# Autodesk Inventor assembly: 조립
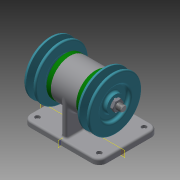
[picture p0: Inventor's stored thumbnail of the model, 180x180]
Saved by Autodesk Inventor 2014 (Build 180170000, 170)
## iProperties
Created: 2019-09
Part Number: 조립
Document SubType Name: Assembly
Designer: kh
Author: kh
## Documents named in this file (10)
- C:\Users\kh\Documents\시험\조립.iam
- C:\Users\kh\Documents\시험\본체.ipt
- C:\Users\kh\Documents\시험\V-벨트풀리.ipt
- C:\Users\kh\Documents\시험\너트 M10x1.ipt
- C:\Users\kh\Documents\시험\베어링 6004.ipt
- C:\Users\kh\Documents\시험\볼트 M4.ipt
- C:\Users\kh\Documents\시험\오일 실 17 30 5.ipt
- C:\Users\kh\Documents\시험\축.ipt
- C:\Users\kh\Documents\시험\커버.ipt
- C:\Users\kh\Documents\시험\키 5 x 5 x 12.ipt
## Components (2 placed, 1 different names)
1. V-벨트풀리:1 — Insert:8, Mate:1, Insert:14
2. V-벨트풀리:2 — Insert:9, Mate:2, Insert:13
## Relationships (6: Insert 4, Mate 2)
- Insert:8: V-벨트풀리:1
- Insert:9: V-벨트풀리:2
- Mate:1: V-벨트풀리:1
- Mate:2: V-벨트풀리:2
- Insert:13: V-벨트풀리:2
- Insert:14: V-벨트풀리:1
